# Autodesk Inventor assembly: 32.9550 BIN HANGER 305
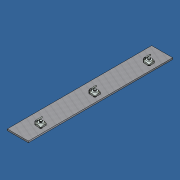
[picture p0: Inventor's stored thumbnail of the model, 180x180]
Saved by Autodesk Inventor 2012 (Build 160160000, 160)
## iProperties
Created: 2013-07
Part Number: 32.9550 BIN HANGER 305
Document SubType Name: Assembly
Designer: Admin
Author: Admin
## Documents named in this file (4)
- C:\Andys Backup Data\ANDY'S INVENTOR\INVENTOR LIBRARIES\PARTS LIBRARY\WORKSTATION\32.9550 BIN HANGER 305.iam
- C:\Andys Backup Data\ANDY'S INVENTOR\INVENTOR LIBRARIES\PARTS LIBRARY\WORKSTATION\SUBCOMPONENTS\32.9550 BIN HANGER 305.ipt
- C:\Andys Backup Data\ANDY'S INVENTOR\INVENTOR LIBRARIES\PARTS LIBRARY\FASTENING ELEMENTS\SCREWS COUNTERSUNK\21.1503 M5X16 CSUNK.IPT
- C:\Andys Backup Data\ANDY'S INVENTOR\INVENTOR LIBRARIES\PARTS LIBRARY\FASTENING ELEMENTS\NUTS\21.1320_2 M5 SQUARE NUT POS FXG.ipt
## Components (7 placed, 3 different names)
1. 32.9550 BIN HANGER 305:1 — Insert:1, Insert:2, Insert:3, Insert:4, Insert:5, Insert:6, Angle:1, Angle:2, Angle:3
2. 21.1503 M5x16 C'SUNK:1 — Insert:1
3. 21.1503 M5x16 C'SUNK:2 — Insert:2
4. 21.1503 M5x16 C'SUNK:3 — Insert:3
5. 21.1320_2 M5 SQUARE NUT POS FXG:1 — Insert:4, Angle:3
6. 21.1320_2 M5 SQUARE NUT POS FXG:2 — Insert:5, Angle:2
7. 21.1320_2 M5 SQUARE NUT POS FXG:3 — Insert:6, Angle:1
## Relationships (9: Insert 6, Angle 3)
- Insert:1: 32.9550 BIN HANGER 305:1 ↔ 21.1503 M5x16 C'SUNK:1
- Insert:2: 32.9550 BIN HANGER 305:1 ↔ 21.1503 M5x16 C'SUNK:2
- Insert:3: 32.9550 BIN HANGER 305:1 ↔ 21.1503 M5x16 C'SUNK:3
- Insert:4: 32.9550 BIN HANGER 305:1 ↔ 21.1320_2 M5 SQUARE NUT POS FXG:1
- Insert:5: 32.9550 BIN HANGER 305:1 ↔ 21.1320_2 M5 SQUARE NUT POS FXG:2
- Insert:6: 32.9550 BIN HANGER 305:1 ↔ 21.1320_2 M5 SQUARE NUT POS FXG:3
- Angle:1: 32.9550 BIN HANGER 305:1 ↔ 21.1320_2 M5 SQUARE NUT POS FXG:3
- Angle:2: 32.9550 BIN HANGER 305:1 ↔ 21.1320_2 M5 SQUARE NUT POS FXG:2
- Angle:3: 32.9550 BIN HANGER 305:1 ↔ 21.1320_2 M5 SQUARE NUT POS FXG:1
